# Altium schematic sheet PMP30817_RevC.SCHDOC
size A4; Date: Not shown in title block; ApprovedBy: Not shown in title block; CheckedBy: Not shown in title block; Author: Not shown in title block; CompanyName: Not shown in title block; Engineer: Not shown in title block; Organization: Not shown in title block; Address1: Not shown in title block; Address2: Not shown in title block; Address3: Not shown in title block; Address4: Not shown in title block; DocumentNumber: 1; Revision: Use project parameter SCH_Rev; SheetNumber: 1; SheetTotal: 1; PageSetup: Record=PageOptions¦CenterHorizontal=True¦CenterVertical=True¦PrintScale=1.00¦XCorrection=1.00¦YCorrection=1.00¦PrintKind=0¦BorderSize=5000000¦LeftOffset=0¦BottomOffset=0¦Orientation=2¦PaperLength=1000¦PaperWidth=1000¦Scale=100¦PaperSource=15¦PrintQuality=600¦MediaType=1¦DitherType=10¦PaperKind=Letter¦PrintScaleMode=1
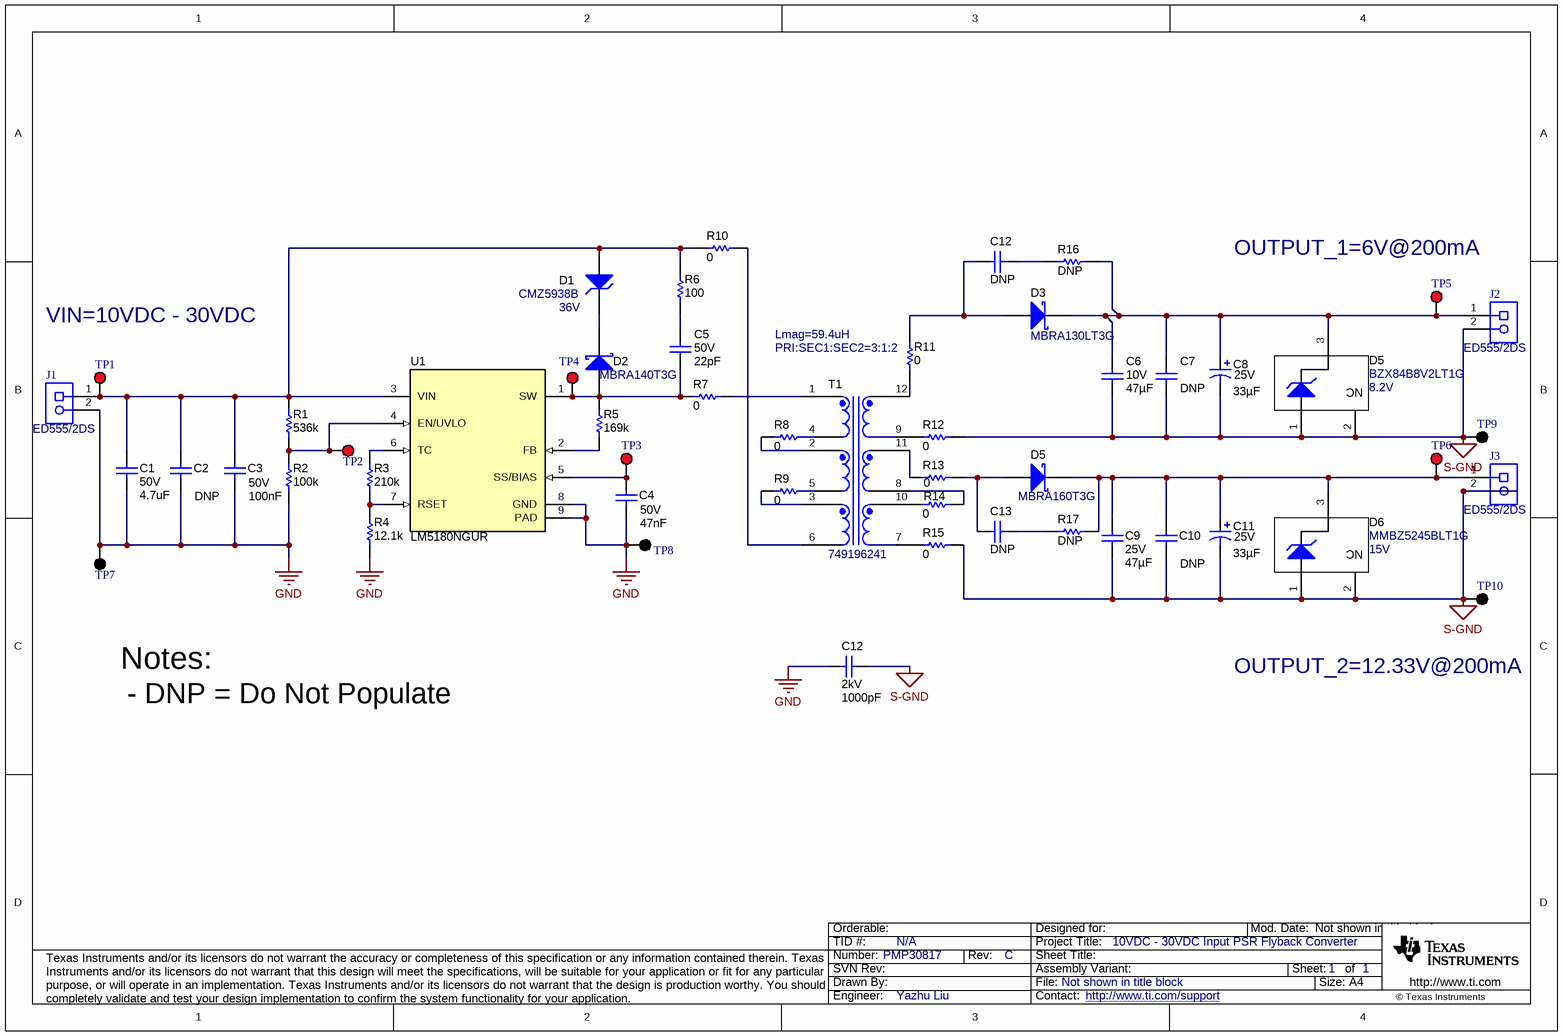
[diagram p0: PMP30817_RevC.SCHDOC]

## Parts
(Parts that share a designator on the sheet are numbered #1, #2 ... from top to bottom, then left to right.)
C1  VDC_V: 50V  ValueDisplayed: 4.7uF  [1206_180]  (hidden comment: C3216X7R1H475K160AC)
C2  PartNumber: DNP  [1210_280]  (hidden comment: C1210C475K5RACAUTO)
C3  Cap_F: 100nF  VDC_V: 50V  [0603]  (hidden comment: C0603C104K5RACAUTO)
C4  Cap_F: 47nF  VDC_V: 50V  [0603]  (hidden comment: C1608X7R1H473K080AA)
C5  VDC_V: 50V  ValueDisplayed: 22pF  [0805]  (hidden comment: 08055A220JAT2A)
C6  VDC_V: 10V  ValueDisplayed: 47µF  [0805]  (hidden comment: GRM21BR61A476ME15L)
C7  PartNumber: DNP  [1206_180]  (hidden comment: C3216X5R1A476M160AB)
C8  Value2: 25V  ValueDisplayed: 33µF  [7343-31]  (hidden comment: T495D336K025ATE090)
C9  VDC_V: 25V  ValueDisplayed: 47µF  [1206]  (hidden comment: GRM31CR61E476ME44L)
C10  PartNumber: DNP  [1206]  (hidden comment: GRM31CR61E476ME44L)
C11  Value2: 25V  ValueDisplayed: 33µF  [7343-31]  (hidden comment: T495D336K025ATE090)
C12#1  VDC_V: DNP  [0805]  (hidden comment: 08055A220JAT2A)
C12#2  VDC_V: 2kV  ValueDisplayed: 1000pF  [1206_180]  (hidden comment: C1206C102KGRACAUTO)
C13  VDC_V: DNP  [0805]  (hidden comment: 08051A220JAT2A)
D1  CMZ5938B  value 36V  [SMA]
D2  MBRA140T3G  [SMA]
D3  MBRA130LT3G  [SMA]
D5#1  BZX84B8V2LT1G  value 8.2V  [SOT-23]
D5#2  MBRA160T3G  [SMA]
D6  MMBZ5245BLT1G  value 15V  [SOT-23]
J1  ED555/2DS  [TERM_BLK_ED555-2DS]
J2  ED555/2DS  [TERM_BLK_ED555-2DS]
J3  ED555/2DS  [TERM_BLK_ED555-2DS]
R1  ValueDisplayed: 536k  [0603]  (hidden comment: RC0603FR-07536KL)
R2  ValueDisplayed: 100k  [0603]  (hidden comment: RC0603FR-07100KL)
R3  ValueDisplayed: 210k  [0603]  (hidden comment: RC0603FR-07210KL)
R4  ValueDisplayed: 12.1k  [0603]  (hidden comment: RC0603FR-0712K1L)
R5  ValueDisplayed: 169k  [0603]  (hidden comment: RT0603BRD07169KL)
R6  ValueDisplayed: 100  [0805]  (hidden comment: RG2012P-101-B-T5)
R7  ValueDisplayed: 0  [0603]  (hidden comment: RK73H1JT)
R8  ValueDisplayed: 0  [0603]  (hidden comment: RK73H1JT)
R9  ValueDisplayed: 0  [0603]  (hidden comment: RK73H1JT)
R10  ValueDisplayed: 0  [0603]  (hidden comment: RK73H1JTL)
R11  ValueDisplayed: 0  [0603]  (hidden comment: RK73H1JT)
R12  ValueDisplayed: 0  [0603]  (hidden comment: RK73H1JT)
R13  ValueDisplayed: 0  [0603]  (hidden comment: RK73H1JT)
R14  ValueDisplayed: 0  [0603]  (hidden comment: RK73H1JT)
R15  ValueDisplayed: 0  [0603]  (hidden comment: RK73H1JT)
R16  ValueDisplayed: DNP  [0805]  (hidden comment: RG2012P-101-B-T5)
R17  ValueDisplayed: DNP  [0805]  (hidden comment: RG2012P-101-B-T5)
T1  749196241  [WURTH_749196211]
TP1  5000  [Keystone5000]  (value not drawn)
TP2  5000  [Keystone5000]  (value not drawn)
TP3  5000  [Keystone5000]  (value not drawn)
TP4  5000  [Keystone5000]  (value not drawn)
TP5  5000  [Keystone5000]  (value not drawn)
TP6  5000  [Keystone5000]  (value not drawn)
TP7  5001  [Keystone5001]  (value not drawn)
TP8  5001  [Keystone5001]  (value not drawn)
TP9  5001  [Keystone5001]  (value not drawn)
TP10  5001  [Keystone5001]  (value not drawn)
U1  LM5180NGUR  [NGU0008C]

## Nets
GND: C1.2 C2.2 C3.2 C4.2 C12#2.2 J1.2 R2.1 R4.1 TP7.1 TP8.1 U1.8(GND) U1.9(PAD)
S-GND: C6.2 C7.2 C8.2(-) C9.2 C10.2 C11.2(-) C12#2.1 D5#1.1(A) D5#1.2(NC) D6.1(A) D6.2(NC) J2.2 J3.2 R12.2 R15.2 TP9.1 TP10.1
NetC1_1: C1.1 C2.1 C3.1 D1.2(A) J1.1 R1.2 R6.2 R10.1 TP1.1 U1.3(VIN)
NetC4_1: C4.1 TP3.1 U1.5(SS/BIAS)
NetC5_1: C5.1 R6.1
NetC5_2: C5.2 D2.2(A) R5.2 R7.1 TP4.1 U1.1(SW)
NetC6_1: C6.1 C7.1 C8.1(+) D3.1(K) D5#1.3(K) J2.1 R16.2 TP5.1
NetC9_1: C9.1 C10.1 C11.1(+) D5#2.1(K) D6.3(K) J3.1 R17.2 TP6.1
NetC12#1_1: C12#1.1 R16.1
NetC12#1_2: C12#1.2 D3.2(A) R11.2
NetC13_1: C13.1 R17.1
NetC13_2: C13.2 D5#2.2(A) R13.2
NetD1_1: D1.1(K) D2.1(K)
NetR1_1: R1.1 R2.2 TP2.1 U1.4(EN/UVLO)
NetR3_1: R3.1 R4.2 U1.7(RSET)
NetR3_2: R3.2 U1.6(TC)
NetR5_1: R5.1 U1.2(FB)
NetR7_2: R7.2 T1.1
NetR8_1: R8.1 T1.2
NetR8_2: R8.2 T1.4
NetR9_1: R9.1 T1.3
NetR9_2: R9.2 T1.5
NetR10_2: R10.2 T1.6
NetR11_1: R11.1 T1.12
NetR12_1: R12.1 T1.9
NetR13_1: R13.1 T1.11
NetR14_1: R14.1 T1.10
NetR14_2: R14.2 T1.8
NetR15_1: R15.1 T1.7

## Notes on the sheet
- (near TP5) OUTPUT_1=6V@200mA
- VIN=10VDC - 30VDC
- Lmag=59.4uH
- (near R11) PRI:SEC1:SEC2=3:1:2
- Notes:
- - DNP = Do Not Populate
- OUTPUT_2=12.33V@200mA
- PMP30817
- N/A
- C
- 10VDC - 30VDC Input PSR Flyback Converter
- Yazhu Liu
- http://www.ti.com/support

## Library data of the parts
C1 = CMP-0008702-1: CAP, CERM, 4.7 uF, 50 V, +/- 10%, X7R, 1206; Manufacturer: TDK; TaMin_C: -55°C; ESR_ohm: 3.158m; Polarized: N; SizeAreaWB_mm2: 10.92; Value1: 0.003158 ohm; U/M: EA; Value: 4.7uF; TaMax_C: 125°C; SizeZ_mm: 1.8; SizeX_mm: 3.2; SizeY_mm: 1.6; SizeArea_mm2: 5.12; Cap_F: 4.7µF; IRMS_A: 4.08379A; AEC Category: Q200
C2 = CMP-0079604-1: CAP, CERM, 4.7 µF, 50 V,+/- 10%, X7R, AEC-Q200 Grade 1, 1210; Manufacturer: Kemet; TaMin_C: -55°C; Polarized: N; SizeAreaWB_mm2: 14.7; U/M: EA; Value: 4.7uF; TaMax_C: 125°C; SizeZ_mm: 2.8; SizeX_mm: 3.2; SizeY_mm: 2.5; Cap_Case: 1210; Value2: 50V; SizeArea_mm2: 8; AEC Qualified: Y; Cap_F: NDP; AEC Grade: 1; AEC Category: Q200
C3 = CMP-0079602-1: CAP, CERM, 0.1 µF, 50 V,+/- 10%, X7R, AEC-Q200 Grade 1, 0603; Manufacturer: Kemet; TaMin_C: -55°C; Polarized: N; SizeAreaWB_mm2: 4.68; U/M: EA; Value: 0.1uF; TaMax_C: 125°C; SizeZ_mm: 1; SizeX_mm: 1.6; SizeY_mm: 0.8; SizeArea_mm2: 1.28; AEC Qualified: Y; AEC Category: Q200; ValueDisplayed: 0.1µF
C4 = CMP-0007049-1: CAP, CERM, 0.047 uF, 50 V, +/- 10%, X7R, 0603; Manufacturer: TDK; TaMin_C: -55°C; ESR_ohm: 0.049007; Polarized: N; SizeAreaWB_mm2: 4.68; Value1: 0.049007 ohm; U/M: EA; TaMax_C: 125°C; SizeZ_mm: 1; SizeX_mm: 1.6; SizeY_mm: 0.8; SizeArea_mm2: 1.28; IRMS_A: 767.528mA; AEC Category: Q200
C5 = CMP-0007599-1: CAP, CERM, 22 pF, 50 V, +/- 5%, C0G/NP0, 0805; Manufacturer: AVX; TaMin_C: -55°C; ESR_ohm: 0.92; Polarized: N; SizeAreaWB_mm2: 6.75; Value1: 0.92 ohm; U/M: EA; Value: 22pF; TaMax_C: 125°C; SizeZ_mm: 1.45; SizeX_mm: 2; SizeY_mm: 1.25; SizeArea_mm2: 2.5; AEC Category: Q200
C6 = CMP-0078699-1: CAP, CERM, 47 µF, 10 V,+/- 20%, X5R, 0805; Manufacturer: MuRata; TaMin_C: -55°C; Polarized: N; Green_Lifecycle: Active; SizeAreaWB_mm2: 6.75; Green_REACh: Passed; U/M: EA; Value: 47uF; TaMax_C: 85°C; SizeZ_mm: 1.45; SizeX_mm: 2; SizeY_mm: 1.25; SizeArea_mm2: 2.5; Cap_F: 47 µF; AEC Category: Q200
C7 = CMP-0008650-1: CAP, CERM, 47 uF, 10 V, +/- 20%, X5R, 1206; Manufacturer: TDK; TaMin_C: -55°C; Polarized: N; SizeAreaWB_mm2: 10.92; Value1: Unknown; U/M: EA; Value: 47; TaMax_C: 85°C; SizeZ_mm: 1.8; SizeX_mm: 3.2; SizeY_mm: 1.6; Cap_Case: 1206; Value2: 10V; SizeArea_mm2: 5.12; Cap_F: 47µF; AEC Category: Q200
C8 C11 = CMP-0011771-2: CAP, TA, 33 uF, 25 V, +/- 10%, 0.09 ohm, SMD; Manufacturer: Kemet; TaMin_C: -55°C; ESR_ohm: 0.09; Polarized: Y; SizeAreaWB_mm2: 58.59; U/M: EA; Value: 33uF; TaMax_C: 125°C; SizeZ_mm: 3.1; SizeX_mm: 7.3; SizeY_mm: 4.3; Cap_Case: D; SizeArea_mm2: 31.39; CompType: Capacitor; IRMS_A: 1.162A; AEC Category: Q200
C9 = CMP-0008646-1: CAP, CERM, 47 uF, 25 V, +/- 20%, JB, 1206; Manufacturer: TDK; TaMin_C: -55°C; Polarized: N; SizeAreaWB_mm2: 10.92; Value1: Unknown; U/M: EA; Value: 47uF; TaMax_C: 85°C; SizeZ_mm: 1.35; SizeX_mm: 3.2; SizeY_mm: 1.6; SizeArea_mm2: 5.12; AEC Category: Q200
C10 = CMP-0008646-1: CAP, CERM, 47 uF, 25 V, +/- 20%, JB, 1206; Manufacturer: TDK; TaMin_C: -55°C; Polarized: N; SizeAreaWB_mm2: 10.92; Value1: Unknown; U/M: EA; Value: DNP; TaMax_C: 85°C; SizeZ_mm: 1.35; SizeX_mm: 3.2; SizeY_mm: 1.6; Value2: 25V; SizeArea_mm2: 5.12; Cap_F: 47µF; AEC Category: Q200
C12#1 = CMP-0007599-1: CAP, CERM, 22 pF, 50 V, +/- 5%, C0G/NP0, 0805; Manufacturer: AVX; TaMin_C: -55°C; ESR_ohm: 0.92; Polarized: N; SizeAreaWB_mm2: 6.75; Value1: 0.92 ohm; U/M: EA; Value: 22pF; TaMax_C: 125°C; SizeZ_mm: 1.45; SizeX_mm: 2; SizeY_mm: 1.25; Value2: 50V; SizeArea_mm2: 2.5; AEC Category: Q200
C12#2 = CMP-0008579-1: CAP, CERM, 1000 pF, 2000 V, +/- 10%, X7R, AEC-Q200 Grade 1, 1206; Manufacturer: Kemet; TaMin_C: -55°C; Polarized: N; SizeAreaWB_mm2: 10.92; Value1: Unknown; U/M: EA; Value: 1000pF; TaMax_C: 125°C; SizeZ_mm: 1.8; SizeX_mm: 3.2; SizeY_mm: 1.6; Cap_Case: 1206; Value2: 2000V; SizeArea_mm2: 5.12; AEC Qualified: Y; Cap_F: 1nF; AEC Grade: 1; AEC Category: Q200
C13 = CMP-0007524-1: CAP, CERM, 22 pF, 100 V, +/- 5%, C0G/NP0, 0805; Manufacturer: AVX; TaMin_C: -55°C; ESR_ohm: 0.92; Polarized: N; SizeAreaWB_mm2: 6.75; Value1: 0.92 ohm; U/M: EA; Value: 22pF; TaMax_C: 125°C; SizeZ_mm: 1.45; SizeX_mm: 2; SizeY_mm: 1.25; Value2: 100V; SizeArea_mm2: 2.5; AEC Category: Q200
D1 = CMP-0082174-1: Diode, Zener, 36V, 1.5 W, SMA; Manufacturer: Taiwan Semiconductor; Power_W: 1.5W; SizeAreaWB_mm2: 37.3428; Vz_V: 150V; Value1: 1.25W; SizeZ_mm: 2.87; SizeX_mm: 5.59; SizeY_mm: 2.92; SizeArea_mm2: 16.3228; AEC Qualified: N; AEC Category: Q101
D2 = CMP-0028550-1: Diode, Schottky, 40 V, 1 A, SMA; Manufacturer: ON Semiconductor; Io_A: 1A; Green_Lifecycle: Not Set; SizeAreaWB_mm2: 37.3428; Vr_V: 40V; Green_REACh: Incomplete; TJmax_C: 125°C; U/M: EA; Value: 40V; SizeZ_mm: 2.87; SizeX_mm: 5.59; SizeY_mm: 2.92; Vf_V: 550mV; Value2: 0.55V; SizeArea_mm2: 16.3228; AEC Category: Q101; RJC_CperW: 35
D3 = CMP-0028549-1: Diode, Schottky, 30 V, 1 A, SMA; Manufacturer: ON Semiconductor; Io_A: 1A; Green_Lifecycle: Active; SizeAreaWB_mm2: 37.3428; Vr_V: 30V; Green_REACh: Passed; TJmax_C: 125°C; U/M: EA; Value: 30V; SizeZ_mm: 2.87; SizeX_mm: 5.59; SizeY_mm: 2.92; Vf_V: 410mV; Value2: 0.41V; SizeArea_mm2: 16.3228; AEC Category: Q101; RJC_CperW: 35
D5#1 = CMP-0005972-1: Diode, Zener, 8.2 V, 225 mW, SOT-23; Manufacturer: ON Semiconductor; Power_W: 225mW; SizeAreaWB_mm2: 14; Value1: 0.225W; RJA_CperW: 556; U/M: EA; SizeZ_mm: 1.1; SizeX_mm: 2.5; SizeY_mm: 3; SizeArea_mm2: 7.5; AEC Category: Q101
D5#2 = CMP-0028551-1: Diode, Schottky, 60 V, 1 A, SMA; Manufacturer: ON Semiconductor; Io_A: 1A; Green_Lifecycle: Not Set; SizeAreaWB_mm2: 37.3428; Vr_V: 60V; Green_REACh: Incomplete; TJmax_C: 150°C; U/M: EA; Value: 60V; SizeZ_mm: 2.87; SizeX_mm: 5.59; SizeY_mm: 2.92; Vf_V: 510mV; Value2: 0.51V; SizeArea_mm2: 16.3228; AEC Category: Q101; RJC_CperW: 35
D6 = CMP-0005953-1: Diode, Zener, 15 V, 225 mW, SOT-23; Manufacturer: ON Semiconductor; Power_W: 225mW; SizeAreaWB_mm2: 14; Value1: 0.225W; RJA_CperW: 556; U/M: EA; SizeZ_mm: 1.1; SizeX_mm: 2.5; SizeY_mm: 3; SizeArea_mm2: 7.5; AEC Category: Q101
J1-J3 = CMP-0074913-1: Terminal Block, 3.5mm Pitch, 2x1, TH; Manufacturer: On-Shore Technology; Cert_VDE: Y; CNHeader: False; Current_A: 6A; Green_Lifecycle: Active; Shrouded: N; Gender: Female; Green_REACh: Passed; Voltage_V: 150V; Row_Count: 1; Pitch_mm: 3.5; ContactFinish: Brass; CT: True
R1 = CMP-0023174-4: RES, 536 k, 1%, 0.1 W, 0603; Manufacturer: Yageo; Power_W: 100mW; TempCo: 100 ppm/C; Value: 536k; EIA_Code: E96; SizeX_mm: 1.6; SizeY_mm: 0.8; SizeZ_mm: 1; Value2: 0.1W; SizeArea_mm2: 1.28; AEC Qualified: N; VDC_V: 75V; AEC Category: Q200; SizeAreaWB_mm2: 4.68
R2 = CMP-0022735-5: RES, 100 k, 1%, 0.1 W, 0603; Manufacturer: Yageo; Power_W: 100mW; TempCo: 100 ppm/C; Value: 100k; EIA_Code: E96; SizeX_mm: 1.6; SizeY_mm: 0.8; SizeZ_mm: 1; Value2: 0.1W; SizeArea_mm2: 1.28; AEC Qualified: N; VDC_V: 75V; AEC Category: Q200; SizeAreaWB_mm2: 4.68
R3 = CMP-0022909-4: RES, 210 k, 1%, 0.1 W, 0603; Manufacturer: Yageo; Power_W: 100mW; TempCo: 100 ppm/C; Value: 210k; EIA_Code: E96; SizeX_mm: 1.6; SizeY_mm: 0.8; SizeZ_mm: 1; Value2: 0.1W; SizeArea_mm2: 1.28; AEC Qualified: N; VDC_V: 75V; AEC Category: Q200; SizeAreaWB_mm2: 4.68
R4 = CMP-0022776-5: RES, 12.1 k, 1%, 0.1 W, 0603; Manufacturer: Yageo; Power_W: 100mW; TempCo: 100 ppm/C; Value_Code: 12k1; Value: 12.1k; EIA_Code: E96; SizeX_mm: 1.6; SizeY_mm: 0.8; SizeZ_mm: 1; Value2: 0.1W; SizeArea_mm2: 1.28; AEC Qualified: N; VDC_V: 75V; AEC Category: Q200; SizeAreaWB_mm2: 4.68
R5 = CMP-0023796-2: RES, 169 k, 0.1%, 0.1 W, 0603; Manufacturer: Yageo America; Power_W: 100mW; TempCo: 25 ppm/C; U/M: EA; Value: 169k; EIA_Code: E192; SizeX_mm: 1.6; SizeY_mm: 0.8; SizeZ_mm: 1; Value2: 0.1W; SizeArea_mm2: 1.28; VDC_V: 75V; AEC Category: Q200
R6 R16 R17 = CMP-0018851-1: RES, 100, 0.1%, 0.125 W, 0805; Manufacturer: Susumu Co Ltd; Power_W: 125mW; TempCo: 25 ppm/C; Value_Code: 100R; U/M: EA; Value: 100; EIA_Code: E192; SizeX_mm: 2; SizeY_mm: 1.25; SizeZ_mm: 1.45; Value2: 0.125W; SizeArea_mm2: 2.5; VDC_V: 100V; AEC Category: Q200
R7-R9 R11-R15 = CMP-0023661-1: RES, 0, 1%, 0.1 W, 0603; Manufacturer: Yageo America; PartNumber: RK73H1JTL; Power_W: 100mW; TempCo: 25 ppm/C; Value_Code: 10R0; Value1: 0.1%; U/M: EA; Value: 10.0; EIA_Code: E192; SizeX_mm: 1.6; SizeY_mm: 0.8; SizeZ_mm: 1; Value2: 0.1W; SizeArea_mm2: 1.28; VDC_V: 75V; AEC Category: Q200
R10 = CMP-0023661-1: RES, 0, 1%, 0.1 W, 0603; Manufacturer: Yageo America; Power_W: 100mW; TempCo: 25 ppm/C; Value_Code: 10R0; Value1: 0.1%; U/M: EA; Value: 10.0; EIA_Code: E192; SizeX_mm: 1.6; SizeY_mm: 0.8; SizeZ_mm: 1; Value2: 0.1W; SizeArea_mm2: 1.28; VDC_V: 75V; AEC Category: Q200
T1 = CMP-0030531-1: Transformer, 21.6uH, SMT; Manufacturer: Wurth Elektronik; LeakageInd_H: 170nH; Value: 6.8uH; Ind_H: 21.6µH; Lp: 21.6; DCR_ohm: 0.159
TP1-TP6 = CMP-0055137-1: Test Point, Miniature, Red, TH; Manufacturer: Keystone; CNHeader: FALSE; Green_Lifecycle: Active; Green_REACh: Passed; ContactFinish: Silver; CT: TRUE
TP7-TP10 = CMP-0055138-1: Test Point, Miniature, Black, TH; Manufacturer: Keystone; CNHeader: FALSE; Green_Lifecycle: Active; Green_REACh: Passed; ContactFinish: Silver; CT: TRUE
U1 = CMP-0084791-1: 70-VIN PSR Flyback DC/DC Converter With 100-V, 1.5-A Integrated Power MOSFET, NGU0008C (WSON-8); Manufacturer: Texas Instruments; Alternate PartNumber: LM5180NGUT; AEC Qualified: N; SizeY_mm: 4; SizeArea_mm2: 16; CompType: IC; SizeAreaWB_mm2: 25; SizeZ_mm: 0.8; AEC Category: Q200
